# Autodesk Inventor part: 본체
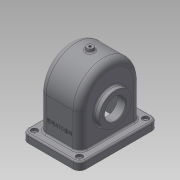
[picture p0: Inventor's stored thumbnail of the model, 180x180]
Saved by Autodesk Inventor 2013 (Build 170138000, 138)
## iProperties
Created: 2016-10
Part Number: 본체
Material: Generic
Document SubType Name: Modeling
Designer: Administrator
Density: 1 g/cm^3
Author: Administrator
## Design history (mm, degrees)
sketch "스케치2"
  geometry: L1 (-38.5, 58)-(38.5, 58); L2 (38.5, 58)-(38.5, -58); L3 (38.5, -58)-(-38.5, -58); L4 (-38.5, -58)-(-38.5, 58); L5 (-38.5, 0)-(38.5, 0); L6 (0, 58)-(0, -58); 1 further point
  constraints: 12 end point, 4 midpoint, 3 perpendicular, 2 parallel, 1 horizontal
  dimensions: "d0" = 77 distance between parallel lines of L2 L4; "d2" = 0 distance from line of point (0, 0) L6; "d3" = 0 distance from line of point (0, 0) L5; "d6" = 38.5 distance between parallel lines of L4 L6 (= 0.5 x d0); "d7" = 58 distance between parallel lines of L5 L1; "d8" = 116 distance between parallel lines of L1 L3 (= 2 x d7)
extrude "돌출1" new body sketch "스케치2" distance "d9" = 80; taper "d10" = 0 deg
sketch "스케치3"
  geometry: L1 (-80, 0)-(-80, 116) reference; L2 (0, 0)-(-80, 0) reference; A1 r 52 centre (-80, 58) between (-80, 110) and (-80, 6); A2 r 58 centre (-80, 58) between (-80, 116) and (-80, 0); 1 further point
  constraints: 4 point on circle, 2 centre point, 2 end point, 2 point on line, 1 midpoint
  dimensions: "d11" = 104 diameter of A1
extrude "돌출2" join sketch "스케치3" stored distance "d15" = 80; taper "d16" = 0 deg
feature "쉘1" dims "d17" = 6
sketch "스케치4"
  geometry: L1 (-55, 75)-(55, 75); L2 (55, 75)-(55, -75); L3 (55, -75)-(-55, -75); L4 (-55, -75)-(-55, 75); L5 (-38.5, 58)-(38.5, 58); L6 (38.5, 58)-(38.5, -58); L7 (38.5, -58)-(-38.5, -58); L8 (-38.5, -58)-(-38.5, 58); L9 (0, 58)-(0, -58); L10 (-38.5, 0)-(38.5, 0); 1 further point
  constraints: 20 end point, 4 midpoint, 4 parallel, 2 horizontal, 2 perpendicular
  dimensions: "d18" = 110 distance between parallel lines of L2 L4; "d20" = 150 distance between parallel lines of L3 L1; "d21" = 55 distance between parallel lines of L2 L9 (= 0.5 x d18); "d22" = 75 distance between parallel lines of L3 L10 (= 0.5 x d20)
extrude "돌출3" join sketch "스케치4" distance "d23" = 15; taper "d24" = 0 deg
sketch "스케치5"
  geometry: L1 (80, -75)-(80, 75) reference; C1 r 20 at (15, 0); A1 r 58 centre (0, 0) between (0, 58) and (0, -58) reference; 1 further point
  constraints: 1 centre point
  dimensions: "d25" = 0 vertical distance of A1.centre C1.centre; "d26" = 65 distance from line of L1 C1.centre; "d27" = 40 diameter of C1
extrude "돌출4" cut sketch "스케치5" stored distance "d28" = 15; taper "d29" = 0 deg
sketch "스케치6"
  geometry: C1 r 20 at (15, 0) reference; C2 r 31 at (15, 0); 1 further point
  constraints: 1 centre point, 1 coincident
  dimensions: "d30" = 62 diameter of C2
extrude "돌출5" join sketch "스케치6" distance "d32" = 10; taper "d33" = 0 deg
sketch "스케치7"
  geometry: C1 r 20 at (-15, 0) reference; C2 r 37.5 at (-15, 0); 1 further point
  constraints: 1 centre point, 1 coincident
  dimensions: "d34" = 75 diameter of C2
extrude "돌출6" join sketch "스케치7" distance "d36" = 5; taper "d37" = 0 deg
node "작업 평면1"
sketch "스케치8"
  geometry: L1 (-32.5, 85)-(-32.5, 45) reference; L2 (-32.5, 65)-(-19.5, 65); L3 (-43.5, 45)-(-43.5, 85) reference; L4 (-32.5, 80)-(-32.5, 132) reference; L5 (-19.5, 65)-(-19.5, 93); L6 (-19.5, 93)-(-32.5, 103.908); L7 (-32.5, 103.908)-(-32.5, 65); 1 further point
  constraints: 8 end point, 1 collinear, 1 midpoint, 1 parallel, 1 perpendicular, 1 point on line
  dimensions: "d39" = 24 distance from line of L3 L2.end; "d40" = 28 distance of L2.end L5.end; "d41" = 50 deg angle of L6 L5
revolve "회전1" sketch "스케치8" stored, may be unused: angle "d42" = 90 deg
sketch "스케치9"
  geometry: C1 r 20 at (0, 0) reference; 1 further point
extrude "돌출7" cut sketch "스케치9" stored distance "d43" = 5; taper "d44" = 0 deg
fillet "모깎기1" dims "d45" = 12
fillet "모깎기2" dims "d46" = 3
sketch "스케치10"
  geometry: C1 r 6 at (-43, -63); C2 r 6 at (-43, 63); C3 r 6 at (43, 63); C4 r 6 at (43, -63); A1 r 9 centre (43, -63) between (43, -72) and (52, -63) reference; A2 r 9 centre (43, 63) between (52, 63) and (43, 72) reference; A3 r 9 centre (-43, 63) between (-43, 72) and (-52, 63) reference; A4 r 9 centre (-43, -63) between (-52, -63) and (-43, -72) reference; 1 further point
  constraints: 4 centre point, 4 coincident, 3 equal radius
  dimensions: "d47" = 12 diameter of C1
extrude "돌출8" cut sketch "스케치10" distance "d49" = 5; taper "d50" = 0 deg
sketch "스케치11"
  geometry: C1 r 6 at (0, 0) reference; C2 r 2.5 at (0, 0); C3 r 6 at (0, 126) reference; C4 r 6 at (86, 126) reference; C5 r 6 at (86, 0) reference; C6 r 2.5 at (0, 126); C7 r 2.5 at (86, 126); C8 r 2.5 at (86, 0); 1 further point
  constraints: 4 centre point, 4 coincident, 3 equal radius
  dimensions: "d51" = 5 diameter of C2
extrude "돌출9" cut sketch "스케치11" stored distance "d53" = 5; taper "d54" = 0 deg
fillet "모깎기3" dims "d55" = 13
fillet "모깎기4" dims "d56" = 3
chamfer "모따기1" distance "d57" = 1; stored, may be unused: second distance "d58" = 2, angle "d59" = 45 deg
fillet "모깎기5" dims "d60" = 8
sketch "스케치12"
  geometry: L1 (-2.004, -34.009)-(53.004, -34.009); L2 (53.004, -34.009)-(53.004, -45.991); L3 (53.004, -45.991)-(-2.004, -45.991); L4 (-2.004, -45.991)-(-2.004, -34.009); L5 (-2.004, -40)-(53.004, -40); L6 (25.5, -34.009)-(25.5, -45.991); L7 (51, 58)-(0, 58) reference; L8 (-17.5, -80)-(68.5, -80) reference; L9 (25.5, 58)-(25.5, -80)
  constraints: 6 end point, 5 midpoint, 1 perpendicular, 2 other
  dimensions: "d61" = 0 distance between parallel lines of L9 L6; "d63" = 40 distance between parallel lines of L8 L5
feature "엠보싱1" sketch "스케치12" dims "d0" = 77, "d2" = 0, "d3" = 0, "d6" = 38.5 (= 0.5 x d0), "d7" = 58, "d8" = 116 (= 2 x d7), "d64" = 0.5, "d65" = 0
fillet "모깎기6" dims "d66" = 3
node "작업 평면2"
sketch "스케치13"
  geometry: C1 r 6 at (0, 0); 1 further point
  constraints: 1 centre point, 1 coincident
  dimensions: "d68" = 12 diameter of C1
extrude "돌출10" join sketch "스케치13" stored distance "d70" = 5; taper "d71" = 10 deg
sketch "스케치14"
  geometry: C1 r 6 at (0, 0) reference
hole "구멍1" sketch "스케치14" at (0, 0) diameter "d72" = 4.459; stored, may be unused: countersink angle "d76" = 90 deg, drill point angle "d78" = 118 deg; dims "d73" = 6, "d74" = 4, "d75" = 2, "d77" = 8
fillet "모깎기7" dims "d79" = 3
sketch "스케치15" dims "d80" = 52
  geometry: C1 r 31 at (0, 0) reference; C2 r 21 at (0, 0) reference; C3 r 1.5 at (0, 26); 2 further points
  constraints: 2 vertical alignment, 1 centre point, 1 coincident, 2 other
  dimensions: "d83" = 3 diameter of C3
hole "구멍2" sketch "스케치15" at (0, 26) diameter "d84" = 2.459; stored, may be unused: countersink angle "d88" = 90 deg, drill point angle "d90" = 118 deg; dims "d85" = 6, "d86" = 4, "d87" = 2, "d89" = 8
sketch "스케치16" dims "d94" = 58
  geometry: C1 r 37.5 at (0, 0) reference; C2 r 21 at (0, 0) reference; C3 r 1.5 at (0, 29); 2 further points
  constraints: 2 vertical alignment, 1 centre point, 1 coincident, 2 other
  dimensions: "d96" = 3 diameter of C3
hole "구멍3" sketch "스케치16" at (0, 29) diameter "d97" = 2.459; stored, may be unused: countersink angle "d101" = 90 deg, drill point angle "d103" = 118 deg; dims "d98" = 6, "d99" = 4, "d100" = 2, "d102" = 8
node "솔리드1"
pattern_circular "원형 패턴1" dims angle "d92" = 360 deg
pattern_circular "원형 패턴2" dims angle "d105" = 360 deg
node "투영된 루프1"
other parameters: "d38" = 0, "d67" = 144
